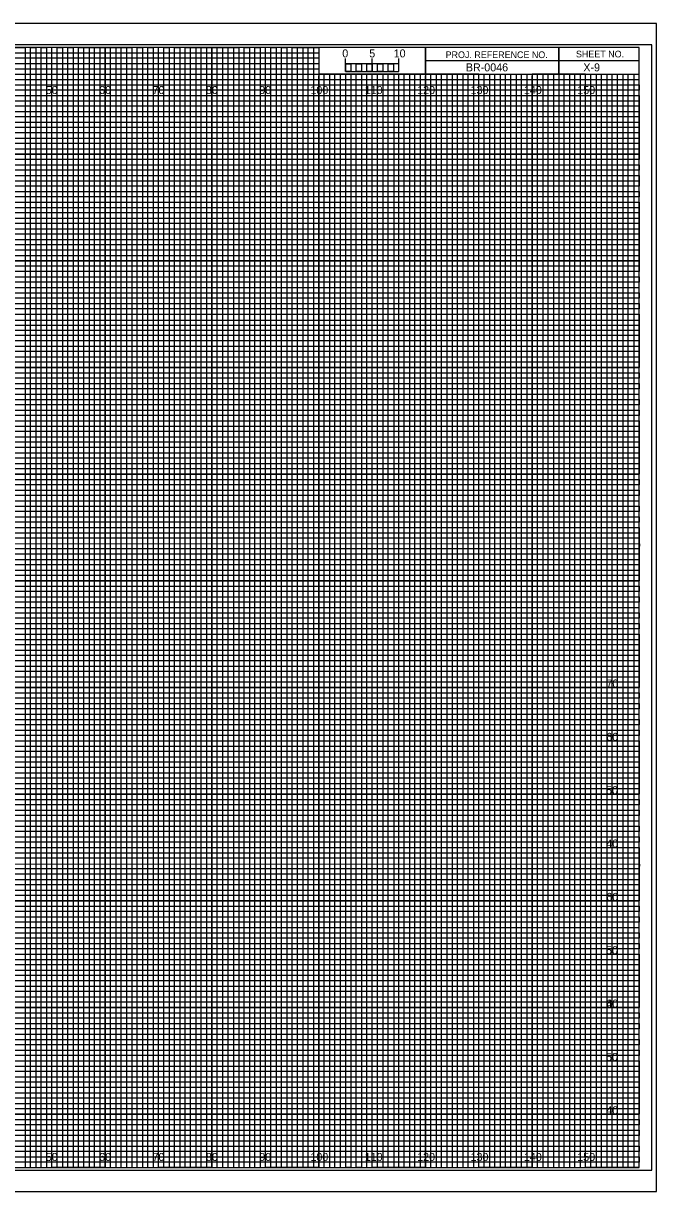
# Model space of a CAD drawing. Extents: x -13 to 323, y -5 to 215.
# Drawn here: x 204.7 to 323.3, y -4.5 to 214.5 of the extents above; entities that cross this region are included whole.
import ezdxf

# ---------------------------------------------------------------- set-up
doc = ezdxf.new("R2010")
doc.units = 0
for name, color, linetype in [('Prop XS Bar Scale Labels', 7, 'Continuous'), ('Prop XS Elevation Labels', 7, 'Continuous'), ('Prop XS Offset Labels', 7, 'Continuous'), ('Prop XS Project Number', 7, 'Continuous'), ('Prop XS Sheet Number', 7, 'Continuous'), ('Sheet Cross Section CELL', 7, 'Continuous'), ('Sheet Cross Section Grid Major CELL', 7, 'Continuous'), ('Sheet Cross Section Grid Middle CELL', 7, 'Continuous'), ('Sheet Cross Section Grid Minor 1 CELL', 7, 'Continuous'), ('Sheet Cross Section Grid Minor 2 CELL', 7, 'Continuous'), ('Sheet Cross Section Scale CELL', 7, 'Continuous'), ('Sheet Cutting Line CELL', 7, 'Continuous'), ('Sheet DOT Grid CELL', 7, 'Continuous'), ('Sheet Plot Border Inside CELL', 7, 'Continuous'), ('Sheet Plot Border Outside CELL', 7, 'Continuous')]:
    doc.layers.add(name, color=color, linetype=linetype)

msp = doc.modelspace()

# ---------------------------------------------------------------- linework, layer by layer
at = {"layer": 'Sheet Cross Section CELL'}
for p, q in [((305, 210), (305, 205)), ((305, 205), (305, 210)), ((280, 207.5), (280, 205)), ((320, 207.49), (280, 207.49)), ((280, 205), (320, 205))]:
    msp.add_line(p, q, dxfattribs=at)
for points in [[(320, 210), (0, 210), (0, 0), (320, 0)], [(280, 210), (260, 210), (260, 205.03), (280, 205.03)], [(320, 210), (280, 210), (280, 205), (320, 205)]]:
    msp.add_lwpolyline(points, close=True, dxfattribs=at)
at = {"layer": 'Sheet Cross Section Grid Major CELL'}
for p, q in [((210, 210), (200, 210)), ((210, 0), (210, 210)), ((230, 210), (220, 210)), ((220, 210), (220, 0)), ((230, 0), (230, 210)), ((250, 210), (240, 210)), ((240, 210), (240, 0)), ((250, 0), (250, 210)), ((260, 210), (260, 0)), ((270, 0), (270, 205)), ((290, 205), (280, 205)), ((280, 205), (280, 0)), ((290, 0), (290, 205)), ((310, 205), (300, 205)), ((300, 205), (300, 0)), ((310, 0), (310, 205)), ((220, 0), (210, 0)), ((240, 0), (230, 0)), ((260, 0), (250, 0)), ((280, 0), (270, 0)), ((300, 0), (290, 0)), ((320, 0), (310, 0)), ((320, 0), (320, 0))]:
    msp.add_line(p, q, dxfattribs=at)
for points in [[(0, 200), (320, 200), (320, 190), (0, 190)], [(0, 180), (320, 180), (320, 170), (0, 170)], [(0, 160), (320, 160), (320, 150), (0, 150)], [(0, 140), (320, 140), (320, 130), (0, 130)], [(0, 120), (320, 120), (320, 110), (0, 110)], [(0, 100), (320, 100), (320, 90), (0, 90)], [(0, 80), (320, 80), (320, 70), (0, 70)], [(0, 60), (320, 60), (320, 50), (0, 50)], [(0, 40), (320, 40), (320, 30), (0, 30)], [(0, 20), (320, 20), (320, 10), (0, 10)]]:
    msp.add_lwpolyline(points, dxfattribs=at)
at = {"layer": 'Sheet Cross Section Grid Middle CELL'}
for points in [[(195, 210), (205, 210), (205, 0), (215, 0), (215, 210), (225, 210), (225, 0), (235, 0), (235, 210), (245, 210), (245, 0), (255, 0), (255, 210), (259.93, 210), (260, 210), (260, 205), (264.99, 205), (264.99, 0), (275, 0), (275, 205), (285, 205), (285, 0), (295, 0), (295, 205), (305, 205), (305, 0), (315, 0), (315, 205)], [(0, 205), (275, 205)], [(0, 185), (320, 185), (320, 195), (0, 195)], [(0, 165), (320, 165), (320, 175), (0, 175)], [(0, 145), (320, 145), (320, 155), (0, 155)], [(0, 125), (320, 125), (320, 135), (0, 135)], [(0, 105), (320, 105), (320, 115), (0, 115)], [(0, 85), (320, 85), (320, 95), (0, 95)], [(0, 65), (320, 65), (320, 75), (0, 75)], [(0, 45), (320, 45), (320, 55), (0, 55)], [(0, 25), (320, 25), (320, 35), (0, 35)], [(0, 5), (320, 5), (320, 15), (0, 15)]]:
    msp.add_lwpolyline(points, dxfattribs=at)
at = {"layer": 'Sheet Cross Section Grid Minor 1 CELL'}
for p, q in [((0, 209), (260, 209)), ((260, 209), (260, 207.98)), ((260, 207.98), (0, 207.98)), ((0, 207), (260, 207)), ((260, 205.89), (0, 205.89)), ((260, 207), (260, 205.89)), ((0, 204), (320, 204))]:
    msp.add_line(p, q, dxfattribs=at)
for points in [[(0, 203), (270, 203), (320, 203), (320, 202), (0, 202)], [(0, 201), (320, 201), (320, 199), (0, 199)], [(0, 198), (320, 198), (320, 197), (0, 196.98)], [(0, 196), (320, 196), (320, 194), (0, 194)], [(0, 193), (320, 193), (320, 192), (0, 192)], [(0, 191), (320, 191), (320, 189), (0, 189)], [(0, 188), (320, 188), (320, 187), (0, 187)], [(0, 186), (320, 186), (320, 184), (0, 184)], [(0, 183), (320, 183), (320, 182), (0, 182)], [(0, 181), (320, 181), (320, 179), (0, 179)], [(0, 178), (320, 178), (320, 177), (0, 177)], [(0, 176), (320, 176), (320, 173.95), (320, 173), (320, 172), (0, 172)], [(0, 174), (320, 174), (320, 173), (0, 173)], [(0, 171), (320, 171), (320, 169), (0, 169.03)], [(0, 169.03), (320, 169), (320, 168), (0, 168)], [(0, 167), (320, 167), (320, 166), (0, 166)], [(0, 164), (320, 164), (320, 163), (0, 163)], [(0, 162), (320, 162), (320, 161), (0, 161)], [(-0.07, 158.89), (320, 158.89), (320, 157.88), (-0.07, 157.88)], [(0, 157), (320, 157), (320, 156), (0, 156)], [(0, 154), (320, 154), (320, 153), (0, 153)], [(0, 152), (320, 152), (320, 151), (0, 151)], [(0, 149), (320, 149), (320, 148), (0, 148)], [(0, 147), (320, 147), (320, 146), (0, 146)], [(0, 144), (320, 144), (320, 143), (0, 143)], [(0, 142), (320, 142), (320, 141), (0, 141)], [(0, 139), (320, 139), (319.99, 137.98), (0, 138)], [(0, 137), (320, 137), (320, 136), (0, 136)], [(0, 134), (320, 134), (320, 133), (0, 133)], [(0, 132), (320, 132), (320, 131), (0, 131)], [(0, 129), (320, 129), (320, 128), (0, 128)], [(0, 127), (320, 127), (320, 126), (0, 126)], [(0, 124), (320, 124), (320, 123), (0, 123)], [(0, 122), (320, 122), (320, 121), (0, 121)], [(0, 119), (320, 119), (320, 118), (0, 118)], [(0, 116.99), (320.07, 116.91), (320, 116), (0, 116)], [(0, 114), (320, 114), (320, 113), (0, 113)], [(0, 112), (320, 112), (320, 111), (0, 111)], [(0, 109), (320, 109), (320, 108), (0, 108)], [(0, 107), (320, 107), (320, 106), (0, 106)], [(0, 104), (320, 104), (320, 103), (0, 103)], [(0, 102), (320, 102), (320, 101), (0, 101)], [(0, 99), (320, 99), (320, 98), (0, 98)], [(0, 97), (320, 97), (320, 96), (0, 96)], [(0, 94), (320, 94), (320, 93), (0, 93)], [(0, 92), (320, 92), (320, 91), (0, 91)], [(0, 89), (320, 89), (320, 88), (0, 88)], [(0, 87), (320, 87), (320, 86), (0, 86)], [(0, 84), (320, 84), (320, 83), (0, 83)], [(0, 82), (320, 82), (320, 81), (0, 81)], [(0, 79), (320, 79), (319.99, 77.98), (0, 78)], [(0, 77), (320, 77), (320, 76), (0, 76)], [(0, 74), (320, 74), (320, 73), (0, 73)], [(0, 72), (320, 72), (320, 71), (0, 71)], [(0, 69), (320, 69), (320, 68), (0, 68)], [(0, 67), (320, 67), (320, 66), (0, 66)], [(0, 64), (320, 64), (320, 63), (0, 63)], [(0, 62), (320, 62), (320, 61), (0, 61)], [(0, 59), (320, 59), (320, 58), (0, 58)], [(0, 56.99), (320.07, 56.91), (320, 56), (0, 56)], [(0, 54), (320, 54), (320, 53), (0, 53)], [(0, 52), (320, 52), (320, 51), (0, 51)], [(0, 49), (320, 49), (320, 48), (0, 48)], [(0, 47), (320, 47), (320, 46), (0, 46)], [(0, 44), (320, 44), (320, 43), (0, 43)], [(0, 42), (320, 42), (320, 41), (0, 41)], [(0, 39), (320, 39), (320, 38), (0, 38)], [(0, 37), (320, 37), (320, 36), (0, 36)], [(0, 34), (320, 34), (320, 33), (0, 33)], [(0, 32), (320, 32), (320, 31), (0, 31)], [(0, 29), (320, 29), (320, 28), (0, 28)], [(0, 27), (320, 27), (320, 26), (0, 26)], [(0, 24), (320, 24), (320, 23), (0, 23)], [(0, 22), (320, 22), (320, 21), (0, 21)], [(0, 19), (320, 19), (320, 18), (0, 18)], [(0, 17), (320, 17), (320, 16), (0, 16)], [(0, 14), (320, 14), (320, 13), (0, 13)], [(0, 12), (320, 12), (320, 11), (0, 11)], [(0, 9), (320, 9), (320, 8), (0, 8)], [(0, 7), (320, 7), (320, 6), (0, 6)], [(0, 4), (320, 4), (320, 3), (0, 3)], [(0, 2), (320, 2), (320, 1), (0, 1)]]:
    msp.add_lwpolyline(points, dxfattribs=at)
at = {"layer": 'Sheet Cross Section Grid Minor 2 CELL'}
for p, q in [((267, 205), (266.01, 205)), ((266.01, 205), (266.01, 0)), ((267, 0), (267, 205)), ((269, 205), (268, 205)), ((268, 205), (268, 0)), ((269, 0), (269, 205)), ((266.01, 0), (265, 0)), ((268, 0), (267, 0))]:
    msp.add_line(p, q, dxfattribs=at)
for points in [[(205, 0), (206, 0), (206, 210), (207, 210), (207, 0)], [(207, 0), (208, 0), (208, 210), (209, 210), (209, 0)], [(210, 0), (211, 0), (211, 210), (212, 210), (212, 0)], [(212, 0), (213, 0), (213, 210), (214, 210), (214, 0)], [(215, 0), (216, 0), (216, 210), (217, 210), (217, 0)], [(217, 0), (218, 0), (218, 210), (219, 210), (219, 0)], [(220, 0), (221, 0), (221, 210), (222, 210), (222, 0)], [(222, 0), (223, 0), (223, 210), (224, 210), (224, 0)], [(225, 0), (226, 0), (226, 210), (227, 210), (227, 0)], [(227, 0), (228, 0), (228, 210), (229, 210), (229, 0)], [(230, 0), (231, 0), (231, 210), (232, 210), (232, 0)], [(232, 0), (233, 0), (233, 210), (234, 210), (234, 0)], [(235, 0), (236, 0), (236, 210), (237, 210), (237, 0)], [(237, 0), (238, 0), (238, 210), (239, 210), (239, 0)], [(240, 0), (241, 0), (241, 210), (242, 210), (242, 0)], [(242, 0), (243, 0), (243, 210), (244, 210), (244, 0)], [(245, 0), (246, 0), (246, 210), (247, 210), (247, 0)], [(247, 0), (248, 0), (248, 210), (249, 210), (249, 0)], [(250, 0), (251, 0), (251, 210), (252, 210), (252, 0)], [(252, 0), (253, 0), (253, 210), (254, 210), (254, 0)], [(255, 0), (256, 0), (256, 210), (257, 210), (257, 0)], [(257, 0), (258, 0), (258, 210), (259, 210), (259, 0)], [(260, 0), (261, 0), (261, 205), (262.02, 205), (262.02, 0)], [(262, 0), (263, 0), (263, 205), (263.99, 205), (263.99, 0)], [(270, 0), (270.98, 0), (270.98, 205), (272, 205), (272, 0)], [(272, 0), (273, 0), (273, 205), (274.05, 205), (274.05, 0)], [(275, 0), (276, 0), (276, 205), (277, 205), (277, 0)], [(277, 0), (278, 0), (278, 205), (279, 205), (279, 0)], [(280, 0), (281, 0), (281, 205), (282, 205), (282, 0)], [(282, 0), (283, 0), (283, 205), (284, 205), (284, 0)], [(285, 0), (286, 0), (286, 205), (287, 205), (287, 0)], [(287, 0), (288, 0), (288, 205), (289, 205), (289, 0)], [(290, 0), (291, 0), (291, 205), (292, 205), (292, 0)], [(292, 0), (293, 0), (293, 205), (294, 205), (294, 0)], [(295, 0), (296, 0), (296, 205), (297, 205), (297, 0)], [(297, 0), (298, 0), (298, 205), (299, 205), (299, 0)], [(300, 0), (301, 0), (301, 205), (302, 205), (302, 0)], [(302, 0), (303, 0), (303, 205), (304, 205), (304, 0)], [(305, 0), (306, 0), (306, 205), (307, 205), (307, 0)], [(307, 0), (308, 0), (308, 205), (309, 205), (309, 0)], [(310, 0), (311, 0), (311, 205), (312, 205), (312, 0)], [(312, 0), (313, 0), (313, 205), (314, 205), (314, 0)], [(315, 0), (316, 0), (316, 205), (317, 205), (317, 0)], [(317, 0), (318, 0), (318, 205), (319, 205), (319, 0)]]:
    msp.add_lwpolyline(points, dxfattribs=at)
at = {"layer": 'Sheet Cross Section Scale CELL'}
for p, q in [((265, 205.49), (265, 207.9)), ((265, 206.9), (265, 207.9)), ((270, 205.49), (270, 207.9)), ((275, 205.49), (275, 207.9)), ((275, 206.9), (275, 207.9))]:
    msp.add_line(p, q, dxfattribs=at)
for points in [[(275, 206.9), (265, 206.9), (265, 205.49), (275, 205.49)], [(265, 206.9), (266, 206.9), (266, 205.49), (265, 205.49)], [(267, 206.9), (268, 206.9), (268, 205.49), (267, 205.49)], [(269, 206.9), (270, 206.9), (270, 205.49), (269, 205.49)], [(271, 206.9), (272, 206.9), (272, 205.49), (271, 205.49)], [(273, 206.9), (274, 206.9), (274, 205.49), (273, 205.49)]]:
    msp.add_lwpolyline(points, close=True, dxfattribs=at)
at = {"layer": 'Sheet Cutting Line CELL'}
for p, q in [((323.3, 214.5), (-13.4, 214.5)), ((-13.4, -4.5), (323.3, -4.5))]:
    msp.add_line(p, q, dxfattribs=at)
at = {"layer": 'Sheet DOT Grid CELL'}
for p, q in [((210, 0), (210, 210)), ((220, 0), (220, 210)), ((230, 0), (230, 210)), ((240, 0), (240, 210)), ((250, 0), (250, 210)), ((260, 0), (260, 204.69)), ((270, 0), (270, 204.69)), ((280, 0), (280, 204.69)), ((290, 0), (290, 204.69)), ((300, 0), (300, 204.69)), ((310, 0), (310, 204.69)), ((0, 200), (320, 200)), ((0, 190), (320, 190)), ((0, 180), (320, 180)), ((0, 170), (320, 170)), ((0, 160), (320, 160)), ((0, 150), (320, 150)), ((0, 140), (320, 140)), ((0, 130), (320, 130)), ((0, 120), (320, 120)), ((0, 110), (320, 110)), ((0, 100), (320, 100)), ((0, 90), (320, 90)), ((0, 80), (320, 80)), ((0, 70), (320, 70)), ((0, 60), (320, 60)), ((0, 50), (320, 50)), ((0, 40), (320, 40)), ((0, 30), (320, 30)), ((0, 20), (320, 20)), ((0, 10), (320, 10))]:
    msp.add_line(p, q, dxfattribs=at)
at = {"layer": 'Sheet Plot Border Inside CELL'}
msp.add_lwpolyline([(-10.8, -0.5), (322.4, -0.5), (322.4, 210.5), (-10.8, 210.5)], close=True, dxfattribs=at)
at = {"layer": 'Sheet Plot Border Outside CELL'}
msp.add_lwpolyline([(-13.4, -4.5), (323.3, -4.5), (323.3, 214.5), (-13.4, 214.5)], close=True, dxfattribs=at)

# ---------------------------------------------------------------- texts
at = {"layer": 'Prop XS Bar Scale Labels'}
for s, p in [('5', (269.47, 208.12)), ('10', (274.04, 208.12))]:
    msp.add_text(s, height=1.5, dxfattribs=at).set_placement(p)
at = {"layer": 'Prop XS Elevation Labels'}
for s, p in [('70', (313.9, 90)), ('60', (313.87, 80)), ('50', (313.82, 70)), ('40', (313.87, 60)), ('60', (313.87, 50)), ('50', (313.82, 40)), ('40', (313.87, 30)), ('60', (313.87, 30)), ('50', (313.82, 20)), ('40', (313.87, 10))]:
    msp.add_text(s, height=1.5, dxfattribs=at).set_placement(p)
at = {"layer": 'Prop XS Offset Labels'}
for s, p in [('50', (208.86, 201.25)), ('60', (218.86, 201.25)), ('70', (228.86, 201.25)), ('80', (238.86, 201.25)), ('90', (248.86, 201.25)), ('100', (258.44, 201.25)), ('110', (268.62, 201.25)), ('120', (278.44, 201.25)), ('130', (288.44, 201.25)), ('140', (298.44, 201.25)), ('150', (308.44, 201.25)), ('50', (208.86, 1.25)), ('60', (218.86, 1.25)), ('70', (228.86, 1.25)), ('80', (238.86, 1.25)), ('90', (248.86, 1.25)), ('100', (258.44, 1.25)), ('110', (268.62, 1.25)), ('120', (278.44, 1.25)), ('130', (288.44, 1.25)), ('140', (298.44, 1.25)), ('150', (308.44, 1.25))]:
    msp.add_text(s, height=1.5, dxfattribs=at).set_placement(p)
at = {"layer": 'Prop XS Project Number'}
msp.add_text('BR-0046', height=1.5, dxfattribs=at).set_placement((287.56, 205.5))
at = {"layer": 'Prop XS Sheet Number'}
msp.add_text('X-9', height=1.5, dxfattribs=at).set_placement((309.57, 205.5))
at = {"layer": 'Sheet Cross Section CELL'}
for s, p in [('PROJ. REFERENCE NO.', (283.77, 207.99)), ('SHEET NO.', (308.19, 208.12))]:
    msp.add_text(s, height=1.25, dxfattribs=at).set_placement(p)
at = {"layer": 'Sheet Cross Section Scale CELL'}
msp.add_text('0', height=1.5, dxfattribs=at).set_placement((264.41, 208.12))

doc.saveas('drawing.dxf')
